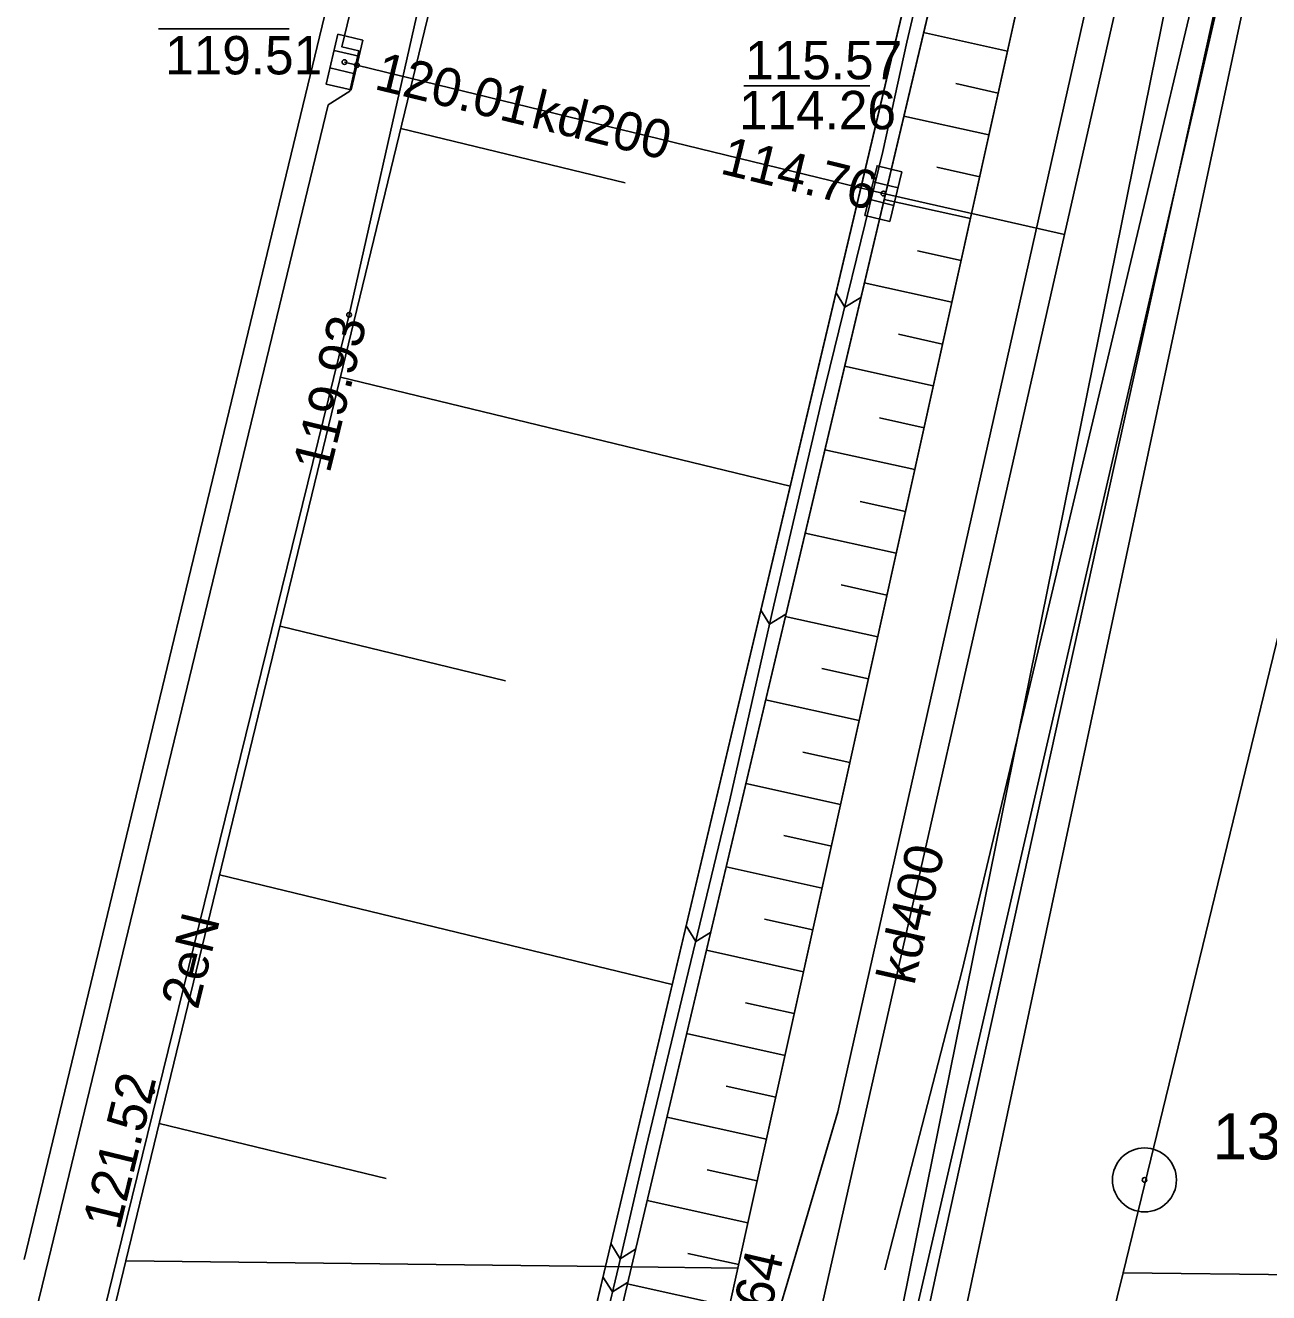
# Model space of a CAD drawing. Extents: x 6424617 to 6425697, y 5665845 to 5667190.
# Drawn here: x 6425383.8 to 6425408.09, y 5666563.12 to 5666587.89 of the extents above; entities that cross this region are included whole.
import ezdxf

# ---------------------------------------------------------------- set-up
doc = ezdxf.new("R2010")
doc.units = 0
for name, color, linetype in [('Warstwa 1', 7, 'Continuous'), ('Warstwa 12', 7, 'Continuous'), ('Warstwa 13', 7, 'Continuous'), ('Warstwa 14', 7, 'Continuous'), ('Warstwa 15', 7, 'Continuous'), ('Warstwa 2', 7, 'Continuous'), ('Warstwa 20', 7, 'Continuous'), ('Warstwa 21', 7, 'Continuous'), ('Warstwa 25', 7, 'Continuous'), ('Warstwa 3', 7, 'Continuous'), ('Warstwa 4', 7, 'Continuous'), ('Warstwa 6', 7, 'Continuous'), ('Warstwa 8', 7, 'Continuous'), ('Warstwa 9', 7, 'Continuous')]:
    doc.layers.add(name, color=color, linetype=linetype)

msp = doc.modelspace()

# ---------------------------------------------------------------- linework, layer by layer
at = {"layer": 'Warstwa 1'}
for p, q in [((6425400.851, 5666561.248), (6425407.267, 5666589.052)), ((6425400.851, 5666561.248), (6425407.267, 5666589.052)), ((6425390.68, 5666508.89), (6425407.73, 5666588.9)), ((6425390.68, 5666508.89), (6425407.73, 5666588.9))]:
    msp.add_line(p, q, dxfattribs=at)
at = {"layer": 'Warstwa 12'}
for points in [[(6425400.589, 5666563.562), (6425402.097, 5666569.421), (6425408.541, 5666596.501), (6425409.731, 5666601.15), (6425418.678, 5666638.344), (6425430.852, 5666690.725), (6425440.64, 5666730.583), (6425449.798, 5666769.666), (6425460.497, 5666812.844)], [(6425401.078, 5666563.555), (6425407.372, 5666594.683), (6425410.104, 5666607.42), (6425414.274, 5666622.662), (6425422.449, 5666656.951), (6425423.137, 5666659.672), (6425424.37, 5666665.077), (6425423.114, 5666667.259), (6425426.34, 5666682.661), (6425426.963, 5666686.268), (6425427.349, 5666686.904), (6425431.338, 5666696.626), (6425432.041, 5666698.181), (6425433.493, 5666701.322), (6425441.988, 5666717.572), (6425451.938, 5666730.92), (6425464.349, 5666743.694), (6425443.874, 5666766.111), (6425443.428, 5666768.827), (6425447.038, 5666782.839), (6425452.086, 5666802.372), (6425454.75, 5666812.915)], [(6425421.88, 5666719.91), (6425428.49, 5666716.24), (6425424.55, 5666707.76), (6425420.22, 5666698.06), (6425415.16, 5666683.78), (6425409.42, 5666662.7), (6425405.85, 5666647.84), (6425402.62, 5666635.28), (6425398, 5666615.16), (6425393.51, 5666597.25), (6425390.12, 5666582.23), (6425385.578, 5666563.742)], [(6425439.31, 5666710.23), (6425439.11, 5666709.67), (6425434.12, 5666696.64), (6425428.07, 5666680.14), (6425421.61, 5666661.95), (6425421.41, 5666661.39), (6425421.28, 5666660.8), (6425417.22, 5666642.32), (6425415.08, 5666632.58), (6425413.05, 5666623.36), (6425412.93, 5666622.78), (6425412.79, 5666622.19), (6425408.52, 5666603.31), (6425404.1, 5666583.8), (6425399.522, 5666563.574)], [(6425458.381, 5666641.622), (6425454.07, 5666642.75), (6425446.51, 5666644.52), (6425434.91, 5666647.89), (6425434.89, 5666649.79), (6425418.77, 5666653.95), (6425407.06, 5666604.32), (6425408.03, 5666603.84), (6425407.64, 5666602.13), (6425399.67, 5666566.65), (6425398.761, 5666563.583)], [(6425404.1, 5666583.8), (6425400.56, 5666584.6), (6425390.03, 5666587.17)], [(6425398.761, 5666563.583), (6425397.55, 5666559.5), (6425397.03, 5666557.16), (6425392.45, 5666536.96), (6425386, 5666508.09), (6425382.01, 5666490.27), (6425381.21, 5666479.99), (6425379.9, 5666475.3), (6425381.52, 5666474.89), (6425375.93, 5666454.14), (6425373.99, 5666454.38), (6425373.44, 5666451.82), (6425375.23, 5666451.4), (6425362.43, 5666401.17), (6425355.8, 5666402.66), (6425355.08, 5666402.04), (6425351.66, 5666389.66), (6425350.42, 5666384.46), (6425347.89, 5666373.29), (6425344.69, 5666359.22), (6425346.02, 5666355.28), (6425340.77, 5666330.04), (6425337.023, 5666314.31)], [(6425356.9, 5666527.18), (6425356.599, 5666523.164), (6425382.059, 5666516.809), (6425390.836, 5666515.826), (6425391.397, 5666519.246), (6425391.071, 5666519.861), (6425391.179, 5666521.093), (6425391.943, 5666521.974), (6425400.124, 5666558.836), (6425401.078, 5666563.555)], [(6425381.23, 5666546.82), (6425385.14, 5666561.96), (6425385.578, 5666563.742)], [(6425398.31, 5666558.26), (6425398.45, 5666558.84), (6425399.522, 5666563.574)]]:
    msp.add_lwpolyline(points, dxfattribs=at)
at = {"layer": 'Warstwa 14'}
for p, q in [((6425388.952, 5666587.818), (6425386.4, 5666587.818)), ((6425400.293, 5666586.708), (6425397.831, 5666586.708))]:
    msp.add_line(p, q, dxfattribs=at)
for centre in [(6425390.03, 5666587.17), (6425390.273, 5666587.111), (6425400.317, 5666584.659), (6425400.56, 5666584.6), (6425390.12, 5666582.23)]:
    msp.add_circle(centre, 0.045, dxfattribs=at)
at = {"layer": 'Warstwa 2'}
for points in [[(6425401.605, 5666563.549), (6425408.292, 5666593.91), (6425426.937, 5666668.658), (6425429.315, 5666678.428), (6425440.801, 5666708.49), (6425443.917, 5666714.896), (6425442.454, 5666715.863), (6425448.554, 5666724.576), (6425465.569, 5666741.764), (6425473.115, 5666748.06), (6425496.069, 5666761.71)], [(6425342.431, 5666314.245), (6425342.9, 5666316.26), (6425351.432, 5666353.898), (6425342.677, 5666355.997), (6425354.705, 5666404.396), (6425364.488, 5666402.728), (6425382.828, 5666478.302), (6425401.605, 5666563.549)]]:
    msp.add_lwpolyline(points, dxfattribs=at)
at = {"layer": 'Warstwa 20'}
for points in [[(6425397.717, 5666563.595), (6425408.777, 5666613.558), (6425420.19, 5666662.277), (6425422.263, 5666671.843), (6425425.112, 5666682.265), (6425428.828, 5666692.501), (6425434.133, 5666703.719), (6425439.89, 5666714.579), (6425446.35, 5666724.425), (6425453.458, 5666733.05), (6425459.766, 5666739.488), (6425469.542, 5666749.045), (6425480.164, 5666757.256), (6425501.728, 5666770.441), (6425513.396, 5666776.752), (6425534.779, 5666786.519), (6425541.614, 5666790.023)], [(6425385.761, 5666563.74), (6425392.31, 5666590.737), (6425397.447, 5666612.102), (6425400.744, 5666625.697), (6425405.446, 5666645.158), (6425409.663, 5666662.648)], [(6425326.04, 5666314.442), (6425336.507, 5666357.769), (6425337.041, 5666371.794), (6425341.788, 5666390.934), (6425346.79, 5666410.35), (6425362.358, 5666467.618), (6425366.796, 5666476.821), (6425368.004, 5666481.671), (6425368.42, 5666492.007), (6425372.53, 5666509.068), (6425385.231, 5666561.556), (6425385.761, 5666563.74)], [(6425360.227, 5666389.481), (6425357.543, 5666390.38), (6425360.324, 5666401.493), (6425360.744, 5666404.797), (6425365.513, 5666424.077), (6425372.256, 5666451.264), (6425375.698, 5666464.586), (6425378.78, 5666473.534), (6425381.389, 5666483.96), (6425380.877, 5666489.401), (6425389.561, 5666528.237), (6425397.189, 5666561.21), (6425397.717, 5666563.595)]]:
    msp.add_lwpolyline(points, dxfattribs=at)
at = {"layer": 'Warstwa 21'}
for points in [[(6425395.128, 5666563.627), (6425400.623, 5666586.839), (6425406.117, 5666610.05), (6425418.598, 5666662.716), (6425420.909, 5666672.158), (6425423.939, 5666682.636), (6425427.728, 5666693.051), (6425432.507, 5666703.979), (6425438.572, 5666715.223), (6425444.985, 5666725.25), (6425452.157, 5666734.094), (6425458.51, 5666740.811), (6425468.627, 5666750.422), (6425479.256, 5666758.503), (6425490.733, 5666765.878), (6425500.954, 5666771.865), (6425512.768, 5666777.974), (6425526.98, 5666784.499), (6425534.042, 5666787.773), (6425542.088, 5666792.135)], [(6425541.942, 5666791.484), (6425534.274, 5666787.329), (6425527.192, 5666784.035), (6425512.98, 5666777.53), (6425501.186, 5666771.421), (6425490.985, 5666765.453), (6425479.549, 5666758.097), (6425468.96, 5666750.036), (6425458.864, 5666740.465), (6425452.531, 5666733.767), (6425445.4, 5666724.963), (6425439.007, 5666714.975), (6425432.963, 5666703.75), (6425428.185, 5666692.863), (6425424.416, 5666682.488), (6425421.387, 5666672.029), (6425419.076, 5666662.608), (6425407.511, 5666613.811), (6425395.635, 5666563.62)], [(6425338.781, 5666314.289), (6425342.093, 5666328.629), (6425347.916, 5666354.162), (6425348.109, 5666355.419), (6425348.432, 5666366.657), (6425348.554, 5666369.545), (6425350.265, 5666377.317), (6425350.911, 5666379.876), (6425351.627, 5666381.874), (6425353.464, 5666386.247), (6425353.858, 5666388.451), (6425354.565, 5666392.214), (6425355.215, 5666394.983), (6425357.587, 5666405.034), (6425362.218, 5666424.397), (6425369.236, 5666451.879), (6425372.67, 5666465.301), (6425376.112, 5666474.212), (6425378.491, 5666484.102), (6425377.911, 5666489.644), (6425387.002, 5666528.883), (6425394.525, 5666561.078), (6425395.128, 5666563.627)], [(6425359.81, 5666387.02), (6425354.35, 5666388.333), (6425355.063, 5666392.105), (6425355.693, 5666394.875), (6425357.414, 5666402.106), (6425358.065, 5666404.925), (6425362.696, 5666424.268), (6425369.714, 5666451.75), (6425373.147, 5666465.152), (6425376.589, 5666474.063), (6425378.991, 5666484.073), (6425378.41, 5666489.615), (6425387.48, 5666528.774), (6425395.003, 5666560.949), (6425395.635, 5666563.62)]]:
    msp.add_lwpolyline(points, dxfattribs=at)
at = {"layer": 'Warstwa 25'}
msp.add_circle((6425386.271, 5666567.049), 0.045, dxfattribs=at)
at = {"layer": 'Warstwa 3'}
for radius in [0.625, 0.045]:
    msp.add_circle((6425405.66, 5666565.32), radius, dxfattribs=at)
at = {"layer": 'Warstwa 4'}
for p, q in [((6425390.313, 5666587.283), (6425389.827, 5666587.398)), ((6425390.233, 5666586.942), (6425389.747, 5666587.057)), ((6425400.845, 5666584.71), (6425400.359, 5666584.83)), ((6425400.761, 5666584.37), (6425400.275, 5666584.49))]:
    msp.add_line(p, q, dxfattribs=at)
for points in [[(6425390.388, 5666587.599), (6425390.159, 5666586.626), (6425389.672, 5666586.741), (6425389.901, 5666587.714)], [(6425400.922, 5666585.026), (6425400.683, 5666584.055), (6425400.198, 5666584.174), (6425400.437, 5666585.145)]]:
    msp.add_lwpolyline(points, close=True, dxfattribs=at)
at = {"layer": 'Warstwa 6'}
for points in [[(6425352.06, 5666353.98), (6425364.93, 5666402.71), (6425390.68, 5666508.89), (6425407.73, 5666588.9), (6425429.67, 5666678.16), (6425441.06, 5666708.4), (6425451.88, 5666727.39), (6425465.93, 5666741.65), (6425473.47, 5666747.98), (6425474.6, 5666748.65), (6425522.252, 5666945.035)], [(6425471.236, 5666853.116), (6425454.155, 5666782.149), (6425453.13, 5666778.441), (6425450.35, 5666766.844), (6425449.817, 5666764.101), (6425447.915, 5666756.464), (6425424.332, 5666659.157), (6425420.309, 5666643.115), (6425407.267, 5666589.052), (6425400.851, 5666561.248), (6425393.198, 5666530.378), (6425392.009, 5666527.133), (6425381.456, 5666483.847), (6425377.52, 5666465.123), (6425363.818, 5666408.694), (6425353.441, 5666367.596)], [(6425353.441, 5666367.596), (6425363.818, 5666408.694), (6425377.52, 5666465.123), (6425381.456, 5666483.847), (6425392.009, 5666527.133), (6425393.198, 5666530.378), (6425400.851, 5666561.248), (6425407.267, 5666589.052), (6425348.172, 5666604.865), (6425360.791, 5666657.874), (6425420.309, 5666643.115), (6425424.332, 5666659.157), (6425447.915, 5666756.464), (6425449.817, 5666764.101), (6425450.35, 5666766.844), (6425453.13, 5666778.441), (6425454.155, 5666782.149), (6425437.407, 5666792.342), (6425392.62, 5666819.33)], [(6425386.659, 5666386.227), (6425410.054, 5666482.642), (6425433.754, 5666580.312), (6425463.303, 5666702.097), (6425474.6, 5666748.65), (6425473.47, 5666747.98), (6425465.93, 5666741.65), (6425451.88, 5666727.39), (6425441.06, 5666708.4), (6425429.67, 5666678.16), (6425407.73, 5666588.9), (6425390.68, 5666508.89), (6425364.93, 5666402.71), (6425352.06, 5666353.98)], [(6425384.247, 5666563.758), (6425389.71, 5666586.333), (6425390.135, 5666586.605), (6425390.309, 5666587.393), (6425389.98, 5666587.468), (6425394.412, 5666605.774), (6425394.837, 5666606.047), (6425395.011, 5666606.834), (6425394.673, 5666606.91), (6425399.105, 5666625.216), (6425399.53, 5666625.488), (6425399.714, 5666626.285), (6425399.375, 5666626.352), (6425401.493, 5666635.036), (6425401.897, 5666635.289), (6425402.082, 5666636.086), (6425401.819, 5666636.491), (6425403.936, 5666645.175), (6425404.265, 5666645.089), (6425404.459, 5666645.876), (6425404.216, 5666646.281), (6425405.611, 5666652.057), (6425406.809, 5666656.907), (6425407.725, 5666660.542)], [(6425383.808, 5666561.942), (6425384.247, 5666563.758)]]:
    msp.add_lwpolyline(points, dxfattribs=at)
at = {"layer": 'Warstwa 8'}
for p, q in [((6425383.772, 5666563.763), (6425403.546, 5666645.693)), ((6425405.241, 5666563.505), (6425419.26, 5666621.16)), ((6425380.18, 5666460.18), (6425405.241, 5666563.505)), ((6425405.241, 5666563.505), (6425418.634, 5666563.343)), ((6425405.241, 5666563.505), (6425412.697, 5666563.415))]:
    msp.add_line(p, q, dxfattribs=at)
at = {"layer": 'Warstwa 9'}
for p, q in [((6425401.02, 5666587.562), (6425401.964, 5666591.658)), ((6425400.548, 5666585.421), (6425401.02, 5666587.562)), ((6425402.983, 5666587.384), (6425401.344, 5666587.747)), ((6425402.802, 5666586.566), (6425401.977, 5666586.749)), ((6425402.621, 5666585.748), (6425400.958, 5666586.116)), ((6425391.13, 5666585.874), (6425395.511, 5666584.812)), ((6425399.346, 5666580.509), (6425400.548, 5666585.421)), ((6425402.44, 5666584.93), (6425401.602, 5666585.115)), ((6425402.259, 5666584.112), (6425400.572, 5666584.486)), ((6425402.078, 5666583.294), (6425401.228, 5666583.482)), ((6425401.897, 5666582.476), (6425400.186, 5666582.855)), ((6425399.634, 5666582.661), (6425399.804, 5666582.38)), ((6425400.119, 5666582.572), (6425399.804, 5666582.38)), ((6425401.716, 5666581.658), (6425400.854, 5666581.849)), ((6425401.534, 5666580.84), (6425399.801, 5666581.225)), ((6425389.95, 5666581.01), (6425398.739, 5666578.878)), ((6425398.421, 5666576.552), (6425399.346, 5666580.509)), ((6425401.353, 5666580.022), (6425400.48, 5666580.216)), ((6425401.172, 5666579.205), (6425399.415, 5666579.594)), ((6425400.991, 5666578.387), (6425400.106, 5666578.583)), ((6425400.81, 5666577.569), (6425399.029, 5666577.963)), ((6425400.629, 5666576.751), (6425399.732, 5666576.95)), ((6425397.558, 5666572.751), (6425398.421, 5666576.552)), ((6425398.165, 5666576.455), (6425398.337, 5666576.181)), ((6425398.655, 5666576.381), (6425398.337, 5666576.181)), ((6425400.448, 5666575.933), (6425398.643, 5666576.333)), ((6425388.771, 5666576.146), (6425393.178, 5666575.077)), ((6425400.267, 5666575.115), (6425399.358, 5666575.316)), ((6425400.086, 5666574.297), (6425398.257, 5666574.702)), ((6425399.905, 5666573.479), (6425398.984, 5666573.683)), ((6425399.724, 5666572.661), (6425397.871, 5666573.071)), ((6425396.709, 5666569.213), (6425397.558, 5666572.751)), ((6425399.543, 5666571.843), (6425398.611, 5666572.05)), ((6425387.591, 5666571.283), (6425396.433, 5666569.138)), ((6425399.362, 5666571.025), (6425397.486, 5666571.441)), ((6425396.704, 5666570.285), (6425396.893, 5666569.977)), ((6425399.181, 5666570.207), (6425398.237, 5666570.416)), ((6425397.181, 5666570.154), (6425396.893, 5666569.977)), ((6425399, 5666569.389), (6425397.1, 5666569.81)), ((6425395.927, 5666565.961), (6425396.709, 5666569.213)), ((6425398.819, 5666568.572), (6425397.863, 5666568.783)), ((6425398.638, 5666567.754), (6425396.714, 5666568.179)), ((6425398.456, 5666566.936), (6425397.489, 5666567.15)), ((6425398.275, 5666566.118), (6425396.328, 5666566.549)), ((6425386.411, 5666566.42), (6425390.847, 5666565.345)), ((6425395.382, 5666563.624), (6425395.927, 5666565.961)), ((6425398.094, 5666565.3), (6425397.114, 5666565.517)), ((6425397.913, 5666564.482), (6425395.942, 5666564.918)), ((6425395.234, 5666564.075), (6425395.418, 5666563.779)), ((6425395.717, 5666563.965), (6425395.418, 5666563.779)), ((6425397.732, 5666563.664), (6425396.74, 5666563.884)), ((6425390.871, 5666544.475), (6425395.382, 5666563.624)), ((6425395.081, 5666563.428), (6425395.265, 5666563.13)), ((6425395.563, 5666563.314), (6425395.265, 5666563.13)), ((6425397.551, 5666562.846), (6425395.556, 5666563.288))]:
    msp.add_line(p, q, dxfattribs=at)
for points in [[(6425409.663, 5666662.648), (6425405.446, 5666645.158), (6425400.744, 5666625.697), (6425397.447, 5666612.102), (6425392.31, 5666590.737), (6425385.761, 5666563.74), (6425395.128, 5666563.627), (6425400.623, 5666586.839), (6425406.117, 5666610.05), (6425418.598, 5666662.716)], [(6425418.598, 5666662.716), (6425406.117, 5666610.05), (6425395.128, 5666563.627), (6425395.635, 5666563.62), (6425407.511, 5666613.811), (6425419.076, 5666662.608)], [(6425419.076, 5666662.608), (6425407.511, 5666613.811), (6425395.635, 5666563.62), (6425397.717, 5666563.595), (6425408.777, 5666613.558), (6425420.19, 5666662.277)], [(6425353.464, 5666386.247), (6425353.858, 5666388.451), (6425354.565, 5666392.214), (6425355.215, 5666394.983), (6425357.587, 5666405.034), (6425362.218, 5666424.397), (6425369.236, 5666451.879), (6425372.67, 5666465.301), (6425376.112, 5666474.212), (6425378.491, 5666484.102), (6425377.911, 5666489.644), (6425387.002, 5666528.883), (6425394.525, 5666561.078), (6425395.128, 5666563.627), (6425385.761, 5666563.74), (6425385.231, 5666561.556), (6425372.53, 5666509.068), (6425368.42, 5666492.007), (6425368.004, 5666481.671), (6425366.796, 5666476.821), (6425362.358, 5666467.618), (6425346.79, 5666410.35), (6425341.788, 5666390.934), (6425337.041, 5666371.794)], [(6425395.003, 5666560.949), (6425395.635, 5666563.62), (6425395.128, 5666563.627), (6425394.525, 5666561.078)], [(6425397.189, 5666561.21), (6425397.717, 5666563.595), (6425395.635, 5666563.62), (6425395.003, 5666560.949)]]:
    msp.add_lwpolyline(points, dxfattribs=at)

# ---------------------------------------------------------------- texts
at = {"layer": 'Warstwa 13'}
for s, rotation, p in [('kd200', 346.2842, (6425393.646, 5666585.902)), ('kd400', 77.2462, (6425401.159, 5666569.106)), ('2eN', 76.1977, (6425387.164, 5666568.629))]:
    msp.add_text(s, height=0.75, rotation=rotation, dxfattribs=at).set_placement(p)
at = {"layer": 'Warstwa 14'}
for s, p in [('119.51', (6425386.527, 5666586.93)), ('114.26', (6425397.738, 5666585.857))]:
    msp.add_text(s, height=0.75, dxfattribs=at).set_placement(p)
for s, rotation, p in [('120.01', 346.2842, (6425390.589, 5666586.648)), ('114.76', 346.2842, (6425397.346, 5666584.998)), ('119.93', 76.1977, (6425389.741, 5666579.114))]:
    msp.add_text(s, height=0.75, rotation=rotation, dxfattribs=at).set_placement(p)
at = {"layer": 'Warstwa 15'}
msp.add_text('115.57', height=0.75, dxfattribs=at).set_placement((6425397.858, 5666586.834))
at = {"layer": 'Warstwa 25'}
for s, rotation, p in [('121.52', 76.3638, (6425385.636, 5666564.318)), ('116.64', 76.9769, (6425397.922, 5666560.848))]:
    msp.add_text(s, height=0.75, rotation=rotation, dxfattribs=at).set_placement(p)
at = {"layer": 'Warstwa 4'}
msp.add_text('1313', height=0.9, dxfattribs=at).set_placement((6425406.993, 5666565.72))

doc.saveas('drawing.dxf')
